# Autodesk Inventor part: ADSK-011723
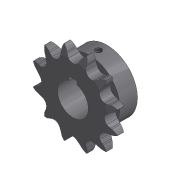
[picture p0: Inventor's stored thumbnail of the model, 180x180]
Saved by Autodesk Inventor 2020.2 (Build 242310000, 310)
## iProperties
Created: 1999-12
Part Number: ADSK-011723
Material: Acier (alliage faible hypertrempé)
Description: SPROCKET,40B12,0.75B,0.18KEY
Document SubType Name: Modeling
Designer: gpurviance
Density: 7.84 g/cm^3
Appearance: Metal-Steel(Polish)
Mass: 167.479 g
Surface Area: 87.5459 cm^2
Volume: 21.3621 cm^3
Control State: 0
Master: False
Checked Out: False
Shininess: 0.0
Length Units: 11269
Angle Units: 11279
Time Units: 11290
Mass Units: 11283
Length Display Precision: 3
Angle Display Precision: 2
Compacted: True
Dimensions: 55x22,2x55 mm
Mass: 0,167 kg
DocNumber: ADSK-011723.ipt
Folder: 01 - Themengebiete\Simplification\01 - Packaging machine\
VDS_Category: 3D Komponenten
VLT_Material: Acier (alliage faible hypertrempé)
Density: 0.0
Volumn: 0.0
Area: 0.0
PropertySet Name: Model Information
Author: gpurviance
Revision Number: -
Title: chainwheel
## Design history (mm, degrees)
node "Sprocket blank" dims "d1" = 7.2136 (= thk), "d2" = 0
node "Sprocket centerline"
node "Hub" dims "d28" = 15.0114 (= hubthk), "d29" = 0
node "Bore extrusion" dims "d31" = 15.0114 (= hubthk), "d32" = 0 (computed from Taper)
  sketch "Sketch6"
    geometry: C1 r 19.844 at (0, 0) reference; C2 r 10 at (0, 0)
    constraints: 1 centre point, 1 coincident
    dimensions: "d30" = 20 diameter of C2
node "Half of tooth shape" dims "d15" = 7.2136 (= thk), "d16" = 0
node "Mirror of tooth half"
node "tooth array" dims "d17" = 120 (= N_1), "d19" = 30 deg (computed from N_1)
node "Revolution2" dims "d46" = 90 deg
node "Extrusion6" dims "d51" = 25.4, "d52" = 0
  sketch "Sketch9"
    geometry: L1 (0, 0)-(0, 10); L2 (0, 10)-(0, 12); L3 (0, 12)-(2.5, 12); L4 (2.5, 12)-(2.5, 8); L5 (2.5, 8)-(-2.5, 8); L6 (-2.5, 8)-(-2.5, 12); L7 (-2.5, 12)-(0, 12); C1 r 19.844 at (0, 0) reference; 1 further point
    constraints: 14 end point, 2 collinear, 2 parallel, 2 perpendicular, 1 vertical, 1 vertical alignment, 1 other
    dimensions: "d47" = 2 distance of L1.end L2.end; "d48" = 5 distance of L4.end L5.end; "d49" = 2.5 distance between parallel lines of L2 L6 (= 0.5 x d48); "d50" = 4 distance between parallel lines of L3 L5
workplane "Work Plane1"
workplane "Work Plane2"
workplane "Work Plane3"
workaxis "Work Axis3"
node "Hole1" dims "d56" = 4.134, "d57" = 9.525, "d58" = 6.35, "d59" = 60 deg, "d60" = 25.4, "d61" = 118 deg, "d63" = 10
workplane "Arbeitsebene5"
node "Solide1"
node "Corps solides"
node "Corps surfaciques"
sketch "Sketch11"
  geometry: L1 (-2.5, 9.682)-(-2.5, 12) reference; L2 (-2.5, 12)-(2.5, 12) reference; L3 (2.5, 12)-(2.5, 9.682) reference; C1 r 19.844 at (0, 0) reference; A1 r 10 centre (0, 0) between (-2.5, 9.682) and (2.5, 9.682) reference
sketch "Sketch1"
  geometry: C1 r 20.572 at (0, 0)
  constraints: 1 centre point
  dimensions: "d0" = 20.57212 radius of C1 (computed from N_1, Pitch, Dr)
sketch "Sketch2" dims "d5" = 7.9248 (= Dr)
  geometry: L1 (0, 24.687)-(0, 0); L2 (0, 0)-(12.343, 21.379); L3 (0, 0)-(6.389, 23.845); L4 (0, 24.535)-(-7.642, 24.535); L5 (3.035, 21.988)-(-4.857, 28.61); L6 (-4.857, 28.61)-(3.779, 24.272); L7 (-14.523, 34.339)-(23.924, 15.03); L8 (4.35, 23.986)-(4.701, 24.684); L9 (30.899, 61.979)-(10.665, 21.689); L10 (7.366, 27.491)-(5.324, 19.871); C1 r 20.572 at (0, 0) reference; A1 r 3.962 centre (0, 24.535) between (0, 20.572) and (3.035, 21.988); A2 r 10.302 centre (-4.857, 28.61) between (3.035, 21.988) and (4.35, 23.986); A3 r 6.674 centre (10.665, 21.689) between (7.366, 27.491) and (4.701, 24.684); A4 r 20.572 centre (0, 0) between (5.324, 19.871) and (0, 20.572)
  constraints: 20 end point, 8 point on circle, 5 point on line, 4 centre point, 3 coincident, 2 equal length, 2 tangent, 1 collinear, 1 horizontal, 1 midpoint, 1 parallel, 1 vertical, 1 vertical alignment, 3 other
  dimensions: "d7" = 15 deg angle of L3 L1 (computed from N_1); "d8" = 15 deg angle of L2 L3 (= d7); "d9" = 40 deg angle of L5 L4 (computed from N_1); "d10" = 13.3333 deg angle of L6 L5 (computed from N_1); "d11" = 6.33984 distance of L4.start L5.end (= 0.8 x Dr); "d12" = 0.78148 distance between parallel lines of L6 L7 (computed from Dr, N_1); "d13" = 24.68654 distance of L1.end L2.end (= 1.2 x d0); "d14" = 6.67431 distance between parallel lines of L9 L8 (computed from N_1, Dr); "d33" = 20.57212 radius of A4 (= d0)
sketch "Sketch5"
  geometry: C1 r 20.572 at (0, 0) reference; C2 r 19.844 at (0, 0)
  constraints: 1 centre point, 1 coincident
  dimensions: "d27" = 39.6875 diameter of C2 (= hubdia)
sketch "Sketch7"
  geometry: L1 (7.214, -7.889)-(7.214, 0) reference; L2 (0, 0)-(7.214, 0) reference; L3 (0, -7.889)-(0, 0) reference; L4 (1.575, 0)-(0, -6.35); L5 (5.639, 0)-(7.214, -6.35); L6 (0, 0)-(-3.607, 0); L7 (-3.607, 0)-(-3.607, -13.564); L8 (-3.607, -13.564)-(0, -13.564); L9 (0, -13.564)-(0, 0); L10 (-19.456, -28.461)-(11.659, -28.461) reference
  constraints: 12 end point, 4 point on line, 2 parallel, 1 horizontal, 1 perpendicular
  dimensions: "d40" = 1.5748 distance from line of L4.start L3 (= G); "d41" = 1.5748 distance from line of L5.start L1 (= G); "d42" = 6.35 distance from line of L5.end L2 (= h); "d43" = 6.35 distance from line of L4.end L2 (= h); "d44" = 7.2136 distance from line of L8 L5.end (= thk); "d45" = 3.6068 distance between parallel lines of L3 L7 (= 0.5 x thk)
sketch "Sketch10"
  geometry: 2 further points
  constraints: 1 coincident
other parameters: "Pitch" = 12.7 [user parameter; used in 1 equation term], "Dr" = 7.9248 [user parameter; used in 5 equation terms], "thk" = 7.2136 [user parameter; used in 4 equation terms], "h" = 6.35 [user parameter; used in 2 equation terms], "G" = 1.5748 [user parameter; used in 2 equation terms], "hubdia" = 39.6875 [user parameter; used in 1 equation term], "hubthk" = 15.0114 [user parameter; used in 2 equation terms], "bore" = 19.05 [user parameter], "Taper" = 0 [user parameter; used in 1 equation term], "d53" = 0, "d54" = -5.715
